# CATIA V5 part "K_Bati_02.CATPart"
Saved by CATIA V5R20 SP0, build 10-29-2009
Part number: Bati_02
Bounding box of the stored display mesh (mm): x -290 to 20, y -284.606 to -279.606, z -219.996 to 219.996
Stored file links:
  G:\Khaled_CFAO_2011\ST2M\ST2M_GR2\jcoetard\Khaled\CAD_CATIA\K_Bati_02.CATPart
  J:\Thinkmotion\Thinkmotion_COETARD\Maquette_catia\Maquette_catia_R20_Licence_education\jcharlescoetard.CATPRODUCT\Assemblage_Pince_Prehension_Mors_Paralleles.CATProduct
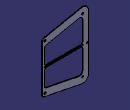
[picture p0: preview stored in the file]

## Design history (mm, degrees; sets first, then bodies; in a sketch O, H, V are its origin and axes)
Set1
  Plane1 "Plan_ref_02": linked copy from another document
  Point1: linked copy from another document
  Point2: linked copy from another document
  Point3 "Point.8": linked copy from another document
  Point4: linked copy from another document
Body1 (main body)
  Sketch1 on Plane1, origin (0, -284.606, 0), H (-1, 0, 0), V (0, 0, 1)
    line L1 (8.0237, 121.014) -> (226.0473, 164.9697)
    point P3 (0, 122.6905)
    line L2 (0, 18) -> (0, 111.2113)
    arc A1 centre (10, 111.2113) radius 10 from (0, 111.2113) to (8.0237, 121.014) cw
    arc A2 centre (230, 145.3642) radius 20 from (226.0473, 164.9697) to (250, 145.3642) cw
    line L3 (250, 145.3642) -> (250, 18)
    line L4 (250, -145.3642) -> (250, -18)
    arc A3 centre (240, -18) radius 10 from (250, -18) to (240, -8) ccw
    line L5 (240, -8) -> (10, -8)
    line L6 (0, 3) -> (250, 3)
    line L7 (250, -3) -> (0, -3)
    point P19 (250, 0)
    arc A4 centre (250, 0) radius 3 from (250, 3) to (250, -3) cw
    arc A5 centre (0, 0) radius 3 from (0, -3) to (0, 3) cw
    line L8 (240, 8) -> (10, 8)
    arc A6 centre (240, 18) radius 10 from (250, 18) to (240, 8) cw
    arc A7 centre (10, 18) radius 10 from (10, 8) to (0, 18) cw
    arc A8 centre (10, -18) radius 10 from (10, -8) to (0, -18) ccw
    line L9 (0, -18) -> (0, -111.2113)
    line L10 (8.0237, -121.014) -> (226.0473, -164.9697)
    arc A9 centre (10, -111.2113) radius 10 from (0, -111.2113) to (8.0237, -121.014) ccw
    arc A10 centre (230, -145.3642) radius 20 from (226.0473, -164.9697) to (250, -145.3642) ccw
    point P33 (290, -110)
    line L11 (290, -110) -> (290, 180)
    arc A11 centre (250, 180) radius 40 from (290, 180) to (242.0947, 219.211) ccw
    line L12 (242.0947, 219.211) -> (-3.9527, 169.6055)
    arc A12 centre (0, 150) radius 20 from (-3.9527, 169.6055) to (-20, 150) ccw
    point P39 (-20, 110)
    line L13 (-20, 150) -> (-20, 110)
    point P41 (290, -110)
    line L14 (290, -110) -> (290, -180)
    arc A13 centre (250, -180) radius 40 from (290, -180) to (242.0947, -219.211) cw
    line L15 (242.0947, -219.211) -> (-3.9527, -169.6055)
    arc A14 centre (0, -150) radius 20 from (-3.9527, -169.6055) to (-20, -150) cw
    point P47 (-20, 110)
    line L16 (-20, -150) -> (-20, 110)
    point P48 (280, 0)
    circle A15 centre (280, 0) radius 4
    construction line L17 (312, 0) -> (-103, 0)
    reference projected point E1 (250, 180) from Point1
    reference projected point E2 (0, 150) from Point2
    reference projected point E3 (250, -180) from Point3
    reference projected point E4 (0, -150) from Point4
    construction line L18 (250, 257) -> (250, -447)
    reference projected point E5 (250, -180) from Point3
    axis line L19 (0, 274) -> (0, -310)
    reference projected point E6 (0, 150) from Point2
    radius A1 = 10
    radius A2 = 20
    radius A11 = 40
    radius A12 = 20
    radius A13 = 40
    radius A10 = 20
    radius A9 = 10
    radius A14 = 20
    radius A3 = 10
    radius A6 = 10
    radius A8 = 10
    radius A7 = 10
    distance L7 L6 = 6
    distance L6 L8 = 5
    distance L6 L17 = 3
    distance P48 L14 = 10
    radius A4 = 3
    radius A5 = 3
    distance L12 L1 = 50
    distance L15 L10 = 50
    horizontal: L17 H
    coincidence: L17 H, P48 L17, P33 P41, P39 P47, L18 P19, L18 L4, L18 L3, L18 E5, L19 L9, L19 L2, L19 E6
    tangency: L3 A2, L1 A2, L2 A1, L1 A1, L12 A11, L11 A11, A12 L12, L13 A12, L3 A6, L2 A7, A7 L8, L8 A6, L4 A3, A3 L5, L5 A8, A8 L9, A9 L9, A9 L10, L10 A10, A10 L4, A13 L14, A13 L15, L15 A14, A14 L16
    concentricity: A11 E1, E2 A12, E3 A13, E4 A14
    vertical: L18 V, L19 V
  Pad1: profile Sketch1, direction (0, 1, 0), length 5
  Sketch2 on start face of Pad1, origin (-250, -284.606, -170), H (1, 0, 0), V (0, 0, 1)
    point P1 (0, -10)
    reference projected point E1 (0, -10) from Point3
    coincidence: E1 P1
  Hole1: placed by Sketch2, at (-250, -284.606, -180) direction (0, 1, 0), diameter 10, depth 10
  Sketch3 on start face of Pad1, origin (0, -284.606, -140), H (1, 0, 0), V (0, 0, 1)
    point P1 (0, -10)
    reference projected point E1 (0, -10) from Point4
    coincidence: E1 P1
  Hole2: placed by Sketch3, at (0, -284.606, -150) direction (0, 1, 0), diameter 10, depth 10
  Sketch4 on start face of Pad1, origin (0, -284.606, 140), H (1, 0, 0), V (0, 0, 1)
    point P1 (0, 10)
    reference projected point E1 (0, 10) from Point2
    coincidence: E1 P1
  Hole3: placed by Sketch4, at (0, -284.606, 150) direction (0, 1, 0), diameter 10, depth 10
  Sketch5 on start face of Pad1, origin (-250, -284.606, 170), H (1, 0, 0), V (0, 0, 1)
    point P1 (0, 10)
    reference projected point E1 (0, 10) from Point1
    coincidence: E1 P1
  Hole4: placed by Sketch5, at (-250, -284.606, 180) direction (0, 1, 0), diameter 10, depth 10
  Fillet1: radius 2, on end face of Pad1; start face of Pad1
